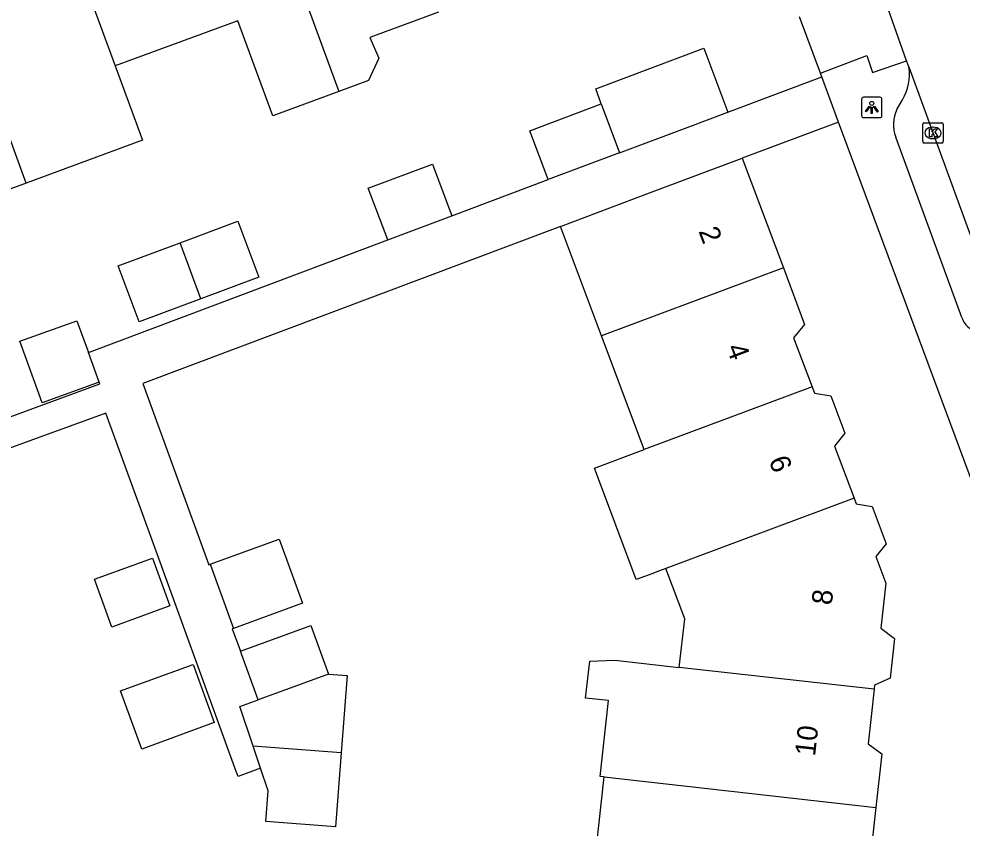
# Model space of a CAD drawing. Extents: x 161258 to 161838, y 380836 to 381727.
# Drawn here: x 161661.92 to 161708.27, y 381426.21 to 381465.96 of the extents above; entities that cross this region are included whole.
import ezdxf

# ---------------------------------------------------------------- set-up
doc = ezdxf.new("R2010")
doc.units = 0
for name, color, linetype in [('IMGEO_Kolk', 7, 'Continuous'), ('IMGEO_Lichtpunt', 7, 'Continuous'), ('IMGEO_Pand', 7, 'Continuous'), ('IMGEO_Pand_nummerreeks', 7, 'Continuous'), ('IMGEO_Rijbaan_lokaal_open', 7, 'Continuous'), ('IMGEO_Voetpad_open', 7, 'Continuous')]:
    doc.layers.add(name, color=color, linetype=linetype)

msp = doc.modelspace()

# ---------------------------------------------------------------- linework, layer by layer
at = {"layer": 'IMGEO_Kolk'}
for p, q in [((161706.337, 381459.931), (161706.337, 381460.783)), ((161706.412, 381460.857), (161707.264, 381460.857)), ((161706.825, 381460.637), (161706.85, 381460.637)), ((161707.338, 381460.783), (161707.338, 381459.931)), ((161707.264, 381459.857), (161706.412, 381459.857)), ((161706.848, 381460.077), (161706.823, 381460.077))]:
    msp.add_line(p, q, dxfattribs=at)
for points in [[(161706.337, 381459.931), (161706.337, 381460.783)], [(161706.412, 381460.857), (161707.264, 381460.857)], [(161707.338, 381460.783), (161707.338, 381459.931)], [(161706.658, 381460.557), (161706.781, 381460.557), (161706.781, 381460.406), (161706.911, 381460.557), (161707.075, 381460.557), (161706.929, 381460.406), (161707.082, 381460.157), (161706.93, 381460.157), (161706.845, 381460.321), (161706.781, 381460.254), (161706.781, 381460.157), (161706.658, 381460.157), (161706.658, 381460.557)], [(161707.264, 381459.857), (161706.412, 381459.857)]]:
    msp.add_lwpolyline(points, dxfattribs=at)
for centre, start, end in [((161706.414, 381460.781), 91.552, 178.448), ((161706.414, 381460.781), 91.552, 178.448), ((161707.262, 381460.781), 1.552, 88.448), ((161707.262, 381460.781), 1.552, 88.448), ((161706.414, 381459.933), 181.552, 268.448), ((161706.414, 381459.933), 181.552, 268.448), ((161707.262, 381459.933), 271.552, 358.448), ((161707.262, 381459.933), 271.552, 358.448)]:
    msp.add_arc(centre, 0.0765, start, end, dxfattribs=at)
for centre, major_axis, ratio, start_param, end_param in [((161706.824, 381460.357), (-0.387, 0.002), 0.722429, 4.712389, 7.853982), ((161706.849, 381460.357), (-0.39, 0.002), 0.717154, 1.570796, 4.712389)]:
    msp.add_ellipse(centre, major_axis=major_axis, ratio=ratio, start_param=start_param, end_param=end_param, dxfattribs=at)
at = {"layer": 'IMGEO_Lichtpunt'}
for p, q in [((161703.332, 381462.008), (161703.332, 381461.201)), ((161703.332, 381462.008), (161703.332, 381461.201)), ((161704.234, 381462.103), (161703.426, 381462.103)), ((161704.234, 381462.103), (161703.426, 381462.103)), ((161704.328, 381461.201), (161704.328, 381462.008)), ((161704.328, 381461.201), (161704.328, 381462.008)), ((161703.426, 381461.107), (161704.234, 381461.107)), ((161703.426, 381461.107), (161704.234, 381461.107))]:
    msp.add_line(p, q, dxfattribs=at)
for points in [[(161703.706, 381461.672), (161703.745, 381461.644), (161703.557, 381461.382), (161703.519, 381461.409), (161703.706, 381461.672)], [(161703.808, 381461.624), (161703.855, 381461.624), (161703.855, 381461.302), (161703.808, 381461.302), (161703.808, 381461.624)], [(161703.918, 381461.644), (161703.956, 381461.671), (161704.143, 381461.409), (161704.104, 381461.381), (161703.918, 381461.644)]]:
    msp.add_lwpolyline(points, dxfattribs=at)
msp.add_circle((161703.831, 381461.806), 0.0994, dxfattribs=at)
for centre, start, end in [((161703.426, 381462.008), 90, 180), ((161703.426, 381462.008), 90, 180), ((161704.234, 381462.008), 0, 90), ((161704.234, 381462.008), 0, 90), ((161703.426, 381461.201), 180, 270), ((161703.426, 381461.201), 180, 270), ((161704.234, 381461.201), 270, 0), ((161704.234, 381461.201), 270, 360)]:
    msp.add_arc(centre, 0.0946, start, end, dxfattribs=at)
at = {"layer": 'IMGEO_Pand'}
for points in [[(161673.154, 381474.595), (161676.142, 381466.5), (161677.653, 381462.391)], [(161663.871, 381471.218), (161666.657, 381463.642)], [(161662.284, 381457.893), (161660.939, 381461.538), (161658.144, 381469.111)], [(161682.544, 381466.28), (161679.175, 381465.037), (161679.612, 381464.021), (161679.11, 381462.928), (161677.653, 381462.391)], [(161677.653, 381462.391), (161674.396, 381461.193), (161672.68, 381465.858), (161666.657, 381463.642)], [(161690.542, 381461.777), (161690.266, 381462.521), (161695.576, 381464.518), (161696.757, 381461.377)], [(161666.657, 381463.642), (161667.998, 381459.995), (161662.284, 381457.893)], [(161687.935, 381458.06), (161687.033, 381460.457), (161690.542, 381461.777)], [(161690.542, 381461.777), (161691.433, 381459.375)], [(161691.433, 381459.375), (161694.766, 381460.628), (161696.757, 381461.377)], [(161691.433, 381459.375), (161687.935, 381458.06)], [(161680.052, 381455.096), (161679.094, 381457.641), (161682.243, 381458.826), (161683.201, 381456.28)], [(161688.53, 381455.758), (161692.779, 381457.36), (161697.459, 381459.12)], [(161697.459, 381459.12), (161699.487, 381453.726)], [(161662.284, 381457.893), (161656.338, 381455.706)], [(161669.851, 381454.956), (161672.682, 381456.013), (161673.707, 381453.268), (161670.862, 381452.206)], [(161680.052, 381455.096), (161683.201, 381456.28)], [(161690.549, 381450.391), (161688.53, 381455.758)], [(161670.862, 381452.206), (161667.834, 381451.076), (161666.81, 381453.821), (161669.851, 381454.956)], [(161670.862, 381452.206), (161669.851, 381454.956)], [(161699.487, 381453.726), (161690.549, 381450.391)], [(161699.487, 381453.726), (161700.532, 381450.947), (161699.991, 381450.289), (161700.897, 381447.88)], [(161665.866, 381448.114), (161663.067, 381447.101), (161662.84, 381447.729), (161661.976, 381450.118), (161664.775, 381451.131), (161665.341, 381449.566)], [(161692.652, 381444.802), (161690.549, 381450.391)], [(161665.866, 381448.114), (161665.341, 381449.566)], [(161700.897, 381447.88), (161692.652, 381444.802)], [(161700.897, 381447.88), (161701.013, 381447.57), (161701.823, 381447.436), (161702.514, 381445.6), (161702, 381444.975), (161702.963, 381442.413)], [(161693.713, 381438.96), (161693.35, 381438.825), (161693.067, 381438.719), (161692.261, 381438.418), (161690.203, 381443.888), (161692.652, 381444.802)], [(161702.963, 381442.413), (161693.713, 381438.96)], [(161702.963, 381442.413), (161703.066, 381442.139), (161703.843, 381442.011), (161704.537, 381440.165), (161704.027, 381439.544), (161704.518, 381438.234), (161704.273, 381436.021), (161704.948, 381435.524), (161704.731, 381433.565), (161703.968, 381433.23), (161703.945, 381433.024)], [(161671.324, 381439.17), (161674.712, 381440.405), (161675.86, 381437.254), (161672.472, 381436.019)], [(161666.496, 381436.079), (161665.64, 381438.428), (161668.494, 381439.468), (161669.35, 381437.119), (161666.496, 381436.079)], [(161671.324, 381439.17), (161672.472, 381436.019)], [(161694.374, 381434.1), (161694.64, 381436.494), (161693.713, 381438.96)], [(161672.808, 381434.902), (161676.27, 381436.164), (161677.142, 381433.77)], [(161673.68, 381432.508), (161672.808, 381434.902)], [(161666.924, 381432.944), (161670.483, 381434.241), (161671.522, 381431.39), (161667.962, 381430.093), (161666.924, 381432.944)], [(161690.682, 381428.718), (161690.478, 381428.74), (161690.892, 381432.469), (161689.77, 381432.593), (161689.97, 381434.403), (161691.198, 381434.455), (161694.374, 381434.1)], [(161677.142, 381433.77), (161673.68, 381432.508)], [(161677.142, 381433.77), (161678.05, 381433.7), (161677.758, 381429.897)], [(161703.945, 381433.024), (161694.374, 381434.1)], [(161703.945, 381433.024), (161703.648, 381430.35), (161704.319, 381429.856), (161704.027, 381427.222)], [(161673.441, 381430.229), (161672.786, 381432.182), (161673.68, 381432.508)], [(161673.803, 381429.149), (161673.441, 381430.229)], [(161677.758, 381429.897), (161673.441, 381430.229)], [(161677.758, 381429.897), (161677.478, 381426.267), (161674.058, 381426.53), (161674.175, 381428.042), (161673.803, 381429.149)], [(161690.466, 381422.857), (161690.037, 381422.905), (161690.682, 381428.718)], [(161690.682, 381428.718), (161704.027, 381427.222)], [(161704.027, 381427.222), (161703.383, 381421.411)]]:
    msp.add_lwpolyline(points, dxfattribs=at)
at = {"layer": 'IMGEO_Rijbaan_lokaal_open'}
for points in [[(161705.542, 381463.901), (161703.946, 381468.421)], [(161705.655, 381463.593), (161705.542, 381463.901)], [(161705.655, 381463.593), (161708.698, 381455.271), (161710.194, 381451.196)]]:
    msp.add_lwpolyline(points, dxfattribs=at)
at = {"layer": 'IMGEO_Voetpad_open'}
for points in [[(161701.306, 381463.287), (161700.279, 381466.054)], [(161701.306, 381463.287), (161703.587, 381464.157), (161703.863, 381463.318), (161705.542, 381463.901)], [(161696.757, 381461.377), (161701.371, 381463.111)], [(161701.371, 381463.111), (161701.306, 381463.287)], [(161702.199, 381460.88), (161701.371, 381463.111)], [(161705.066, 381461.501), (161705.335, 381461.985)], [(161702.199, 381460.88), (161697.459, 381459.12)], [(161703.682, 381379.623), (161710.363, 381438.89), (161702.199, 381460.88)], [(161708.247, 381451.281), (161705.006, 381460.153)], [(161683.201, 381456.28), (161687.935, 381458.06)], [(161688.53, 381455.758), (161668.011, 381448.039), (161671.253, 381439.144), (161671.324, 381439.17)], [(161665.341, 381449.566), (161680.052, 381455.096)], [(161645.597, 381440.484), (161648.418, 381441.597), (161650.576, 381442.391), (161665.897, 381448.031), (161665.866, 381448.114)], [(161673.803, 381429.149), (161672.696, 381428.746), (161672.606, 381428.993), (161668.469, 381440.343), (161666.191, 381446.595), (161647.334, 381439.729)], [(161672.472, 381436.019), (161672.401, 381435.993), (161672.808, 381434.902)]]:
    msp.add_lwpolyline(points, dxfattribs=at)
for centre, radius, start, end in [((161703.29, 381463.228), 2.393, 328.7116, 8.7782), ((161706.552, 381460.76), 1.661, 153.4836, 201.4192), ((161709.309, 381451.68), 1.134, 200.5785, 255.8196)]:
    msp.add_arc(centre, radius, start, end, dxfattribs=at)

# ---------------------------------------------------------------- texts
at = {"layer": 'IMGEO_Pand_nummerreeks'}
for s, rotation, p in [('2', 290.606, (161695.306, 381455.529)), ('4', 290.6527, (161696.671, 381449.806)), ('6', 290.6549, (161698.755, 381444.278)), ('8', 83.6825, (161701.861, 381437.135)), ('10', 83.6598, (161701.042, 381429.714))]:
    msp.add_text(s, height=1, rotation=rotation, dxfattribs=at).set_placement(p)

doc.saveas('drawing.dxf')
